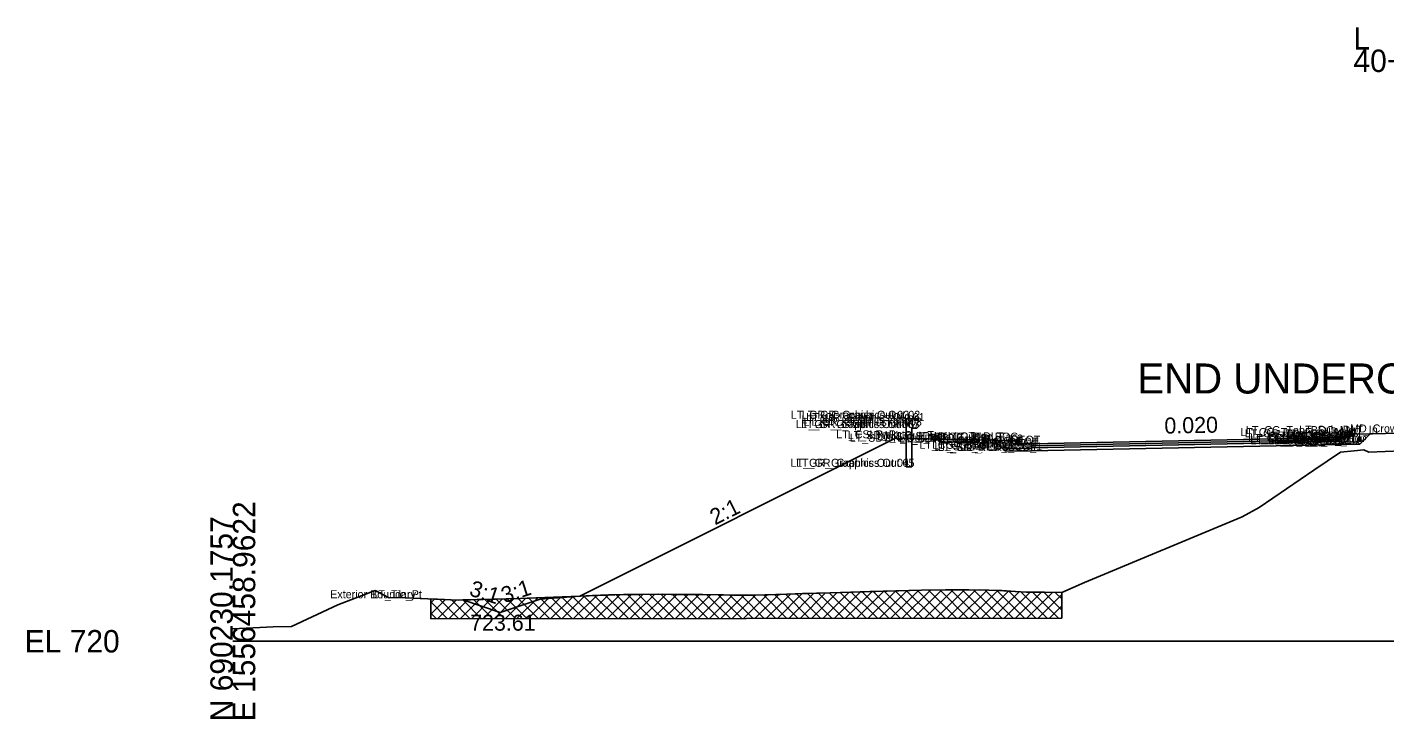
# Model space of a CAD drawing. Extents: x -26 to 6300, y -10 to 9577.
# Drawn here: x -25.7 to 143.9, y 6990.3 to 7076.7 of the extents above; entities that cross this region are included whole.
import ezdxf

# ---------------------------------------------------------------- set-up
doc = ezdxf.new("R2010")
doc.units = 0
for name, color, linetype in [('Default', 7, 'Continuous'), ('Exist Cross Section Cell', 7, 'Continuous'), ('Exist XS Ground Line', 7, 'Continuous'), ('Prop CMT Conc Surface', 7, 'Continuous'), ('Prop CMT Concrete Structures', 7, 'Continuous'), ('Prop CMT Guardrail Graphics', 7, 'Continuous'), ('Prop CMT Pvmt Course 1', 7, 'Continuous'), ('Prop CMT Pvmt Course 1 CG', 7, 'Continuous'), ('Prop CMT Pvmt Course 2', 7, 'Continuous'), ('Prop CMT Pvmt Course 3', 7, 'Continuous'), ('Prop CMT Pvmt Surface', 7, 'Continuous'), ('Prop CMT Slope Grass', 7, 'Continuous'), ('Prop CMT Subgrade Earthwork', 7, 'Continuous'), ('Prop XS DDE', 7, 'Continuous'), ('Prop XS DDE Text', 7, 'Continuous'), ('Prop XS SE Text', 7, 'Continuous'), ('Prop XS Side Slope Text', 7, 'Continuous'), ('Prop XS Undercut Exc', 7, 'Continuous'), ('Prop XS Undercut Exc Hatch', 7, 'Continuous'), ('Prop XSC Text', 7, 'Continuous')]:
    doc.layers.add(name, color=color, linetype=linetype)

msp = doc.modelspace()

# ---------------------------------------------------------------- linework, layer by layer
at = {"layer": 'Exist Cross Section Cell'}
msp.add_line((0, 7000), (150, 7000), dxfattribs=at)
at = {"layer": 'Exist XS Ground Line'}
msp.add_lwpolyline([(0, 7001.56), (5.05, 7001.79), (7.35, 7001.85), (13.1, 7004.53), (17.8, 7006.33), (19.53, 7005.43), (20.58, 7005.47), (28.15, 7005.14), (35.96, 7005.34), (47.71, 7005.81), (49.94, 7005.84), (53.63, 7005.87), (65.15, 7005.75), (73.22, 7006.02), (86.04, 7006.4), (93.24, 7006.43), (95.61, 7006.36), (99.17, 7006.15), (101.39, 7006.12), (103.55, 7006.1), (106.42, 7007.35), (126.09, 7015.56), (128.23, 7016.72), (135.03, 7021.37), (138.38, 7023.63), (140.08, 7023.79), (141.28, 7023.92), (141.93, 7023.62), (146.02, 7023.77)], dxfattribs=at)
at = {"layer": 'Prop CMT Conc Surface'}
for points in [[(138.5, 7025.45), (139.25, 7025.47), (139.25, 7025.63), (140.01, 7025.88)], [(93.24, 7025.15), (88.24, 7025.25)], [(97.79, 7024.56), (97.79, 7025.06), (97.29, 7025.06)], [(99.79, 7024.68), (97.79, 7024.56)]]:
    msp.add_lwpolyline(points, dxfattribs=at)
at = {"layer": 'Prop CMT Concrete Structures'}
for points in [[(138.5, 7025.45), (139.25, 7025.47), (139.25, 7025.63), (140.01, 7025.88)], [(138.5, 7024.87), (138.5, 7025.45)], [(140.01, 7025.88), (140.01, 7024.9)], [(88.24, 7024.92), (88.24, 7025.25)], [(88.24, 7025.25), (93.24, 7025.15)], [(93.24, 7024.82), (88.24, 7024.92)], [(93.24, 7025.15), (93.24, 7024.82)], [(99.79, 7024.68), (97.79, 7024.56), (97.79, 7025.06), (97.29, 7025.06)], [(97.29, 7025.06), (97.29, 7024.05), (99.79, 7024.1)], [(99.79, 7024.1), (99.79, 7024.68)], [(140.01, 7024.9), (138.5, 7024.87)]]:
    msp.add_lwpolyline(points, dxfattribs=at)
at = {"layer": 'Prop CMT Guardrail Graphics'}
for points in [[(84.14, 7021.79), (84.14, 7027.79)], [(84.14, 7027.79), (85.47, 7027.79), (85.75, 7027.5)], [(85.75, 7027.5), (85.47, 7027.21)], [(85.47, 7027.21), (85.75, 7026.92)], [(85.75, 7026.92), (85.47, 7026.63), (84.81, 7026.63)], [(84.81, 7026.63), (84.81, 7021.79)], [(84.81, 7021.79), (84.14, 7021.79)]]:
    msp.add_lwpolyline(points, dxfattribs=at)
at = {"layer": 'Prop CMT Pvmt Course 1'}
for points in [[(138.5, 7025.45), (99.79, 7024.68)], [(138.5, 7025.2), (138.5, 7025.45)], [(99.79, 7024.43), (138.5, 7025.2)], [(99.79, 7024.68), (99.79, 7024.43)], [(138.5, 7025.2), (138.5, 7025.2), (138.5, 7025.2)]]:
    msp.add_lwpolyline(points, dxfattribs=at)
at = {"layer": 'Prop CMT Pvmt Course 1 CG'}
for points in [[(99.79, 7024.1), (96.79, 7024.04), (96.49, 7023.74)], [(96.49, 7023.74), (99.79, 7023.8)], [(99.79, 7023.85), (99.79, 7024.1)], [(138.5, 7024.87), (140.51, 7024.91), (140.8, 7024.62)], [(138.5, 7024.62), (138.5, 7024.87)], [(140.76, 7024.62), (138.5, 7024.58)]]:
    msp.add_lwpolyline(points, dxfattribs=at)
at = {"layer": 'Prop CMT Pvmt Course 2'}
for points in [[(138.5, 7025.2), (99.79, 7024.43)], [(99.79, 7024.18), (138.5, 7024.95)], [(99.79, 7024.43), (99.79, 7024.18)], [(138.5, 7024.95), (138.5, 7025.2)]]:
    msp.add_lwpolyline(points, dxfattribs=at)
at = {"layer": 'Prop CMT Pvmt Course 3'}
for points in [[(138.5, 7024.95), (99.79, 7024.18)], [(99.79, 7023.8), (138.5, 7024.58)], [(99.79, 7024.18), (99.79, 7023.8)], [(138.5, 7024.58), (138.5, 7024.95)]]:
    msp.add_lwpolyline(points, dxfattribs=at)
at = {"layer": 'Prop CMT Pvmt Surface'}
msp.add_lwpolyline([(138.5, 7025.45), (99.79, 7024.68)], dxfattribs=at)
at = {"layer": 'Prop CMT Slope Grass'}
msp.add_line((82.79, 7025.35), (43.37, 7005.64), dxfattribs=at)
for points in [[(140.01, 7025.88), (150, 7026.08)], [(97.29, 7025.06), (82.79, 7025.35)]]:
    msp.add_lwpolyline(points, dxfattribs=at)
at = {"layer": 'Prop CMT Subgrade Earthwork'}
msp.add_line((96.49, 7023.74), (95.13, 7025.1), dxfattribs=at)
for points in [[(142.1, 7025.93), (140.8, 7024.62)], [(99.79, 7023.8), (96.49, 7023.74)], [(138.5, 7024.58), (99.79, 7023.8)], [(140.8, 7024.62), (138.5, 7024.58)], [(138.5, 7024.58), (138.5, 7024.58)]]:
    msp.add_lwpolyline(points, dxfattribs=at)
at = {"layer": 'Prop XS DDE'}
for p, q in [((38.39, 7005.27), (33.39, 7003.61)), ((43.37, 7005.64), (38.39, 7005.27))]:
    msp.add_line(p, q, dxfattribs=at)
msp.add_lwpolyline([(33.39, 7003.61), (28.75, 7005.16)], dxfattribs=at)
at = {"layer": 'Prop XS Undercut Exc'}
for p, q in [((24.75, 7005.29), (24.75, 7002.82)), ((31.24, 7002.82), (33.7, 7005.29)), ((31.5, 7005.23), (33.91, 7002.83)), ((32.66, 7002.82), (35.16, 7005.32)), ((32.88, 7005.26), (35.32, 7002.83)), ((53.14, 7005.87), (50.82, 7005.85)), ((64.83, 7005.75), (62.56, 7005.77)), ((102.02, 7002.89), (103.55, 7004.42)), ((103.43, 7002.89), (103.55, 7003.01))]:
    msp.add_line(p, q, dxfattribs=at)
for points in [[(24.75, 7002.82), (103.55, 7002.89), (103.55, 7006.1)], [(44.94, 7005.7), (43.37, 7005.64), (36.78, 7005.38), (35.96, 7005.34), (28.75, 7005.16), (28.15, 7005.14), (24.75, 7005.29)], [(48.82, 7005.83), (46.92, 7005.78), (44.94, 7005.7)], [(50.82, 7005.85), (49.94, 7005.84), (48.82, 7005.83)], [(58.66, 7005.82), (56.56, 7005.84), (54.77, 7005.86), (53.14, 7005.87)], [(62.56, 7005.77), (60.77, 7005.79), (58.66, 7005.82)], [(66.88, 7005.8), (65.15, 7005.75), (64.83, 7005.75)], [(86.04, 7006.4), (79.63, 7006.21), (74.67, 7006.06), (71.18, 7005.95), (68.4, 7005.86), (66.88, 7005.8)], [(91.96, 7006.42), (89.05, 7006.41), (86.04, 7006.4)], [(97.78, 7006.23), (96.07, 7006.34), (94.43, 7006.4), (91.96, 7006.42)], [(103.55, 7006.1), (101.39, 7006.12), (101, 7006.13), (99.69, 7006.14), (99.17, 7006.15), (97.78, 7006.23)]]:
    msp.add_lwpolyline(points, dxfattribs=at)
at = {"layer": 'Prop XS Undercut Exc Hatch'}
for p, q in [((24.75, 7004.82), (25.2, 7005.27)), ((24.75, 7003.4), (26.56, 7005.21)), ((25.58, 7002.82), (27.91, 7005.15)), ((25.83, 7005.24), (28.25, 7002.82)), ((27, 7002.82), (29.35, 7005.17)), ((27.31, 7005.18), (29.67, 7002.82)), ((28.41, 7002.82), (30.8, 7005.21)), ((28.75, 7005.16), (31.08, 7002.82)), ((29.83, 7002.82), (32.25, 7005.25)), ((30.13, 7005.19), (32.49, 7002.82)), ((34.07, 7002.83), (36.62, 7005.37)), ((34.26, 7005.3), (36.73, 7002.83)), ((35.49, 7002.83), (38.09, 7005.43)), ((35.64, 7005.34), (38.14, 7002.83)), ((36.9, 7002.83), (39.56, 7005.49)), ((37, 7005.39), (39.56, 7002.83)), ((38.32, 7002.83), (41.04, 7005.55)), ((38.36, 7005.44), (40.97, 7002.83)), ((39.72, 7005.5), (42.38, 7002.83)), ((39.74, 7002.83), (42.51, 7005.61)), ((41.08, 7005.55), (43.8, 7002.84)), ((41.15, 7002.83), (43.98, 7005.67)), ((42.44, 7005.6), (45.21, 7002.84)), ((42.57, 7002.83), (45.46, 7005.72)), ((43.8, 7005.66), (46.62, 7002.84)), ((43.98, 7002.84), (46.93, 7005.78)), ((45.16, 7005.71), (48.04, 7002.84)), ((45.4, 7002.84), (48.38, 7005.82)), ((46.52, 7005.77), (49.45, 7002.84)), ((46.81, 7002.84), (49.81, 7005.84)), ((47.9, 7005.81), (50.86, 7002.84)), ((48.23, 7002.84), (51.24, 7005.85)), ((49.29, 7005.83), (52.27, 7002.84)), ((49.64, 7002.84), (52.67, 7005.86)), ((50.69, 7005.85), (53.69, 7002.84)), ((51.06, 7002.84), (54.08, 7005.86)), ((52.09, 7005.86), (55.1, 7002.85)), ((52.48, 7002.84), (55.48, 7005.85)), ((53.49, 7005.87), (56.51, 7002.85)), ((53.89, 7002.84), (56.88, 7005.84)), ((54.92, 7005.86), (57.93, 7002.85)), ((55.31, 7002.85), (58.28, 7005.82)), ((56.35, 7005.84), (59.34, 7002.85)), ((56.72, 7002.85), (59.68, 7005.81)), ((57.78, 7005.83), (60.75, 7002.85)), ((58.14, 7002.85), (61.08, 7005.79)), ((59.21, 7005.81), (62.16, 7002.85)), ((59.55, 7002.85), (62.48, 7005.78)), ((60.64, 7005.8), (63.58, 7002.85)), ((60.97, 7002.85), (63.88, 7005.76)), ((62.07, 7005.78), (64.99, 7002.85)), ((62.38, 7002.85), (65.28, 7005.75)), ((63.5, 7005.76), (66.4, 7002.86)), ((63.8, 7002.85), (66.75, 7005.8)), ((64.92, 7005.75), (67.82, 7002.86)), ((65.22, 7002.86), (68.21, 7005.85)), ((66.3, 7005.78), (69.23, 7002.86)), ((66.63, 7002.86), (69.67, 7005.9)), ((67.67, 7005.83), (70.64, 7002.86)), ((68.05, 7002.86), (71.14, 7005.95)), ((69.04, 7005.88), (72.05, 7002.86)), ((69.46, 7002.86), (72.6, 7006)), ((70.41, 7005.92), (73.47, 7002.86)), ((70.88, 7002.86), (74.06, 7006.04)), ((71.78, 7005.97), (74.88, 7002.86)), ((72.29, 7002.86), (75.52, 7006.09)), ((73.15, 7006.01), (76.29, 7002.87)), ((73.71, 7002.86), (76.98, 7006.13)), ((74.52, 7006.06), (77.71, 7002.87)), ((75.12, 7002.86), (78.43, 7006.17)), ((75.89, 7006.1), (79.12, 7002.87)), ((76.54, 7002.87), (79.89, 7006.22)), ((77.26, 7006.14), (80.53, 7002.87)), ((77.96, 7002.87), (81.35, 7006.26)), ((78.64, 7006.18), (81.94, 7002.87)), ((79.37, 7002.87), (82.81, 7006.3)), ((80.01, 7006.22), (83.36, 7002.87)), ((80.79, 7002.87), (84.26, 7006.35)), ((81.38, 7006.26), (84.77, 7002.87)), ((82.2, 7002.87), (85.72, 7006.39)), ((82.76, 7006.3), (86.18, 7002.87)), ((83.62, 7002.87), (87.15, 7006.4)), ((84.13, 7006.34), (87.6, 7002.88)), ((85.03, 7002.87), (88.57, 7006.41)), ((85.5, 7006.38), (89.01, 7002.88)), ((86.45, 7002.87), (89.99, 7006.42)), ((86.9, 7006.4), (90.42, 7002.88)), ((87.86, 7002.88), (91.41, 7006.42)), ((88.31, 7006.41), (91.84, 7002.88)), ((89.28, 7002.88), (92.82, 7006.41)), ((89.71, 7006.41), (93.25, 7002.88)), ((90.69, 7002.88), (94.22, 7006.4)), ((91.12, 7006.42), (94.66, 7002.88)), ((92.11, 7002.88), (95.59, 7006.35)), ((92.54, 7006.42), (96.07, 7002.88)), ((93.53, 7002.88), (96.93, 7006.29)), ((93.97, 7006.4), (97.49, 7002.89)), ((94.94, 7002.88), (98.26, 7006.2)), ((95.43, 7006.36), (98.9, 7002.89)), ((96.36, 7002.88), (99.62, 7006.14)), ((96.91, 7006.29), (100.31, 7002.89)), ((97.77, 7002.89), (101.01, 7006.13)), ((98.42, 7006.2), (101.73, 7002.89)), ((99.19, 7002.89), (102.41, 7006.11)), ((99.89, 7006.14), (103.14, 7002.89)), ((100.6, 7002.89), (103.55, 7005.84)), ((101.32, 7006.12), (103.55, 7003.89)), ((102.75, 7006.11), (103.55, 7005.31)), ((24.75, 7004.91), (26.84, 7002.82)), ((24.75, 7003.5), (25.43, 7002.82))]:
    msp.add_line(p, q, dxfattribs=at)

# ---------------------------------------------------------------- texts
at = {"layer": 'Default'}
for s, height, p in [('LT_GR_Graphics Out 03', 1, (69.71, 7027.79)), ('LT_GR_Graphics Out 02', 1, (71.08, 7027.79)), ('LT_GR_Graphics Out 06', 1, (70.35, 7026.63)), ('LT_GR_Graphics Out 07', 1, (70.99, 7026.63)), ('LT_GR_Graphics Out 09', 1, (71.03, 7027.21)), ('LT_GR_Graphics Out 08', 1, (71.29, 7026.92)), ('LT_GR_Graphics Out 01', 1, (71.64, 7027.5)), ('MD_Crown Point', 1, (139.58, 7026.08)), ('LT_CSLP_Pnt', 1, (75.39, 7025.35)), ('LT_SDWK_Out_Top', 1, (76.82, 7025.25)), ('LT_SDWK_Out_Bot', 1, (77.07, 7024.92)), ('LT_Sub_Trench_Out_DLT', 1, (80.51, 7025.1)), ('LT_SDWK_In_Top', 1, (82.98, 7025.15)), ('LT_SDWK_In_Bot', 1, (83.23, 7024.82)), ('LT_CG_Top_BOC', 1, (87.1, 7025.06)), ('LT_CG_Top_Face', 1, (87.63, 7025.06)), ('LT_CG_Top_Gut', 1, (88.16, 7024.56)), ('LT_PV2_OEOT', 1, (91.28, 7024.43)), ('LT_PV1_OEOT', 1, (91.52, 7024.68)), ('LT_CG_Top_Face_Med', 1, (125.87, 7025.63)), ('LT_CG_Top_Gut_Med', 1, (126.42, 7025.47)), ('LT_CG_Top_BOC_Med', 1, (126.57, 7025.88)), ('LT_CG_Bot_BOC_Med', 1, (126.85, 7024.9)), ('LT_CG_Bot_IE_Med', 1, (127.09, 7024.87)), ('LT_Sub_IEOT_CG_1', 1, (127.13, 7024.62)), ('LT_PV2_OEEOP', 1, (129.29, 7025.2)), ('LT_PV3_OEEOP', 1, (129.29, 7024.95)), ('LT_Sub_OEEOP', 1, (129.33, 7024.58)), ('LT_PV2_IEEOP', 1, (130.05, 7025.2)), ('LT_Sub_IEEOP', 1, (130.09, 7024.58)), ('LT_CG1_Shelf_In', 1, (130.71, 7024.91)), ('LT_PV2_PGL', 1, (131.26, 7025.2)), ('LT_Sub_PGL', 1, (131.31, 7024.58)), ('LT_PV1_PGL', 1, (131.5, 7025.45)), ('LT_Sub_IEOP', 1, (133.05, 7024.67)), ('LT_Sub_DLT_In', 1, (133.22, 7025.93)), ('LT_CG1_Shelf_Out', 1, (85.77, 7024.04)), ('LT_CG_Bot_BOC', 1, (87.38, 7024.05)), ('LT_Sub_OEOT_CG_1', 1, (87.65, 7023.85)), ('LT_Sub_OEOP', 1, (88.06, 7023.78)), ('LT_PV3_OEOT', 1, (91.28, 7024.18)), ('LT_Sub_OEOT', 1, (91.33, 7023.8)), ('LT_CG_Bot_IE', 1, (91.63, 7024.1)), ('LT_GR_Graphics Out 04', 1, (69.68, 7021.79)), ('LT_GR_Graphics Out 05', 1, (70.37, 7021.79)), ('Exterior Boundary', 1, (12.17, 7005.37)), ('LT_Tie_Pt', 1, (17.45, 7005.37)), ('-', 0.0001, (0, 7000))]:
    msp.add_text(s, height=height, dxfattribs=at).set_placement(p)
at = {"layer": 'Exist Cross Section Cell'}
for s, p in [('L', (140, 7073.91)), ('40+50.00 / 1', (140, 7071.11)), ('EL 720', (-26, 6998.6))]:
    msp.add_text(s, height=2.8, dxfattribs=at).set_placement(p)
for s, p in [('E 1556458.9622', (2.8, 6990)), ('N 690230.1757', (0, 6990))]:
    msp.add_text(s, height=2.8, rotation=90, dxfattribs=at).set_placement(p)
at = {"layer": 'Prop XS DDE Text'}
for rotation, p in [(341.5651, (29.41, 7005.77)), (17.9773, (33.91, 7004.73))]:
    msp.add_text('3:1', height=2, rotation=rotation, dxfattribs=at).set_placement(p)
msp.add_text('723.61', height=2, dxfattribs=at).set_placement((29.65, 7001.32))
at = {"layer": 'Prop XS SE Text'}
msp.add_text('0.020', height=2, rotation=1.1458, dxfattribs=at).set_placement((116.4, 7025.93))
at = {"layer": 'Prop XS Side Slope Text'}
msp.add_text('2:1', height=2, rotation=26.5651, dxfattribs=at).set_placement((60.24, 7014.47))
at = {"layer": 'Prop XSC Text'}
msp.add_text('END UNDERCUT AT STA 40+75', height=3.75, dxfattribs=at).set_placement((113.01, 7030.95))

doc.saveas('drawing.dxf')
